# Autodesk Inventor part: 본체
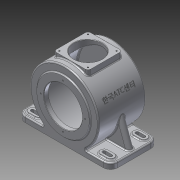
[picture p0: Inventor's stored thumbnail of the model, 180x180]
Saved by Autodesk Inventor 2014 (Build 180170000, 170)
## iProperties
Created: 2015-06
Part Number: 본체
Material: 알루미늄 6061
Document SubType Name: Modeling
Designer: basic
Density: 2.71 g/cm^3
Appearance: 알루미늄 - 평지
Mass: 3237.59 g
Surface Area: 2301.07 cm^2
Volume: 1194.68 cm^3
Author: basic
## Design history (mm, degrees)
sketch "스케치1"
  geometry: L1 (115, 7)-(-115, 7); L2 (-115, 7)-(-115, -7); L3 (-115, -7)-(115, -7); L4 (115, -7)-(115, 7); A1 r 85 centre (0, 78) between (46.733, 7) and (-46.733, 7); 3 further points
  constraints: 8 end point, 2 midpoint, 2 parallel, 2 point on circle, 2 point on line, 2 vertical alignment, 1 centre point, 1 horizontal, 1 horizontal alignment, 1 perpendicular
  dimensions: "d0" = 230 distance of L1.start L1.end; "d1" = 14 distance of L1.end L2.end; "d2" = 170 diameter of A1; "d3" = 85 distance from line of A1.centre L3
extrude "돌출1" new body sketch "스케치1" stored distance "d4" = 118; taper "d5" = 0 deg
sketch "스케치2"
  geometry: C1 r 65 at (0, 78); A1 r 85 centre (0, 78) between (46.733, 7) and (-46.733, 7) reference; 1 further point
  constraints: 1 centre point, 1 coincident
  dimensions: "d6" = 130 diameter of C1
extrude "돌출2" join sketch "스케치2" distance "d7" = 3; taper "d8" = 0 deg
sketch "스케치3"
  geometry: C1 r 65 at (0, -78); A1 r 85 centre (0, -78) between (-46.733, -7) and (46.733, -7) reference; 1 further point
  constraints: 1 centre point, 1 coincident
  dimensions: "d9" = 130 diameter of C1
extrude "돌출3" join sketch "스케치3" distance "d10" = 13; taper "d11" = 0 deg
node "작업 평면1"
sketch "스케치4"
  geometry: L1 (200, 0)-(30, 0) reference; L2 (157.5, -16.5)-(72.5, -16.5); L3 (72.5, -16.5)-(72.5, -101.5); L4 (72.5, -101.5)-(157.5, -101.5); L5 (157.5, -101.5)-(157.5, -16.5); 5 further points
  constraints: 8 end point, 2 midpoint, 2 parallel, 1 horizontal, 1 horizontal alignment, 1 perpendicular, 1 vertical alignment
  dimensions: "d13" = 85 distance of L4.end L3.end; "d14" = 85 distance of L3.end L2.end
extrude "돌출4" join sketch "스케치4" stored distance "d15" = 13; taper "d16" = 0 deg
sketch "스케치5"
  geometry: L1 (68.267, 0)-(68.267, 118) reference; L2 (0, 118)-(68.267, 118) reference; L3 (-161.733, 0)-(-161.733, 118) reference; L4 (68.267, 118)-(-161.733, 118) reference; L5 (68.267, 0)-(68.267, 118) reference; L6 (-161.733, 0)-(68.267, 0) reference; L7 (34.267, 109)-(50.267, 109); L8 (50.267, 91)-(34.267, 91); A1 r 9 centre (50.267, 100) between (50.267, 91) and (50.267, 109); A2 r 9 centre (34.267, 100) between (34.267, 109) and (34.267, 91); 1 further point
  constraints: 4 end point, 4 point on circle, 4 tangent, 2 centre point, 1 horizontal alignment
  dimensions: "d17" = 18 diameter of A1; "d18" = 18 diameter of A2; "d19" = 16 distance of A2.centre A1.centre; "d20" = 18 distance from line of A1.centre L1; "d21" = 18 distance from line of L2 A1.centre
extrude "돌출5" join sketch "스케치5" distance "d22" = 3; taper "d23" = 0 deg
sketch "스케치6"
  geometry: L1 (50.267, 109)-(34.267, 109) reference; L2 (34.267, 104)-(50.267, 104); L3 (50.267, 96)-(34.267, 96); A1 r 9 centre (34.267, 100) between (34.267, 109) and (34.267, 91) reference; A2 r 9 centre (50.267, 100) between (50.267, 91) and (50.267, 109) reference; A3 r 4 centre (50.267, 100) between (50.267, 96) and (50.267, 104); A4 r 4 centre (34.267, 100) between (34.267, 104) and (34.267, 96); 1 further point
  constraints: 4 end point, 4 point on circle, 3 tangent, 2 centre point, 2 coincident, 1 parallel
  dimensions: "d24" = 8 diameter of A3; "d25" = 8 diameter of A4
extrude "돌출6" cut sketch "스케치6" stored distance "d26" = 3; taper "d27" = 0 deg
sketch "스케치7"
  geometry: L1 (115, 7)-(46.733, 7) reference; L2 (-46.733, 7)-(-115, 7) reference; L3 (-115, 7)-(-115, -7) reference; L4 (-115, -7)-(115, -7) reference; L5 (115, -7)-(115, 7) reference; L6 (-109, 7)-(-84.87, 73.297); C1 r 65 at (0, 78) reference; A1 r 85 centre (0, 78) between (46.733, 7) and (-46.733, 7) reference; 1 further point
  constraints: 2 end point, 1 point on circle, 1 point on line
  dimensions: "d28" = 6 distance from line of L3 L6.start; "d29" = 110 deg angle of L2 L6
extrude "돌출7" join sketch "스케치7" stored distance "d30" = 15; taper "d31" = 0 deg
sketch "스케치8"
  geometry: L1 (115, 7)-(46.733, 7) reference; L2 (-46.733, 7)-(-115, 7) reference; L3 (-115, 7)-(-115, -7) reference; L4 (-115, -7)-(115, -7) reference; L5 (115, -7)-(115, 7) reference; C1 r 65 at (0, 78) reference; C2 r 77 at (0, 78); A1 r 85 centre (0, 78) between (46.733, 7) and (-46.733, 7) reference; 1 further point
  constraints: 1 centre point, 1 coincident
  dimensions: "d32" = 154 diameter of C2
extrude "돌출8" cut sketch "스케치8" stored distance "d33" = 102; taper "d34" = 0 deg
sketch "스케치9"
  geometry: C1 r 65 at (0, 0) reference; C2 r 47.5 at (0, 0); 1 further point
  constraints: 1 centre point, 1 coincident
  dimensions: "d35" = 95 diameter of C2
extrude "돌출9" cut sketch "스케치9" distance "d36" = 11; taper "d37" = 0 deg
sketch "스케치10"
  geometry: L1 (7.5, 73.297)-(7.5, 7) reference; L2 (59, 7)-(7.5, 7) reference; L3 (59, 7)-(59, 7) reference; L4 (-59, 7)-(59, 7) reference; L5 (-59, 7)-(-59, 7) reference; L6 (-7.5, 7)-(-59, 7) reference; L7 (-7.5, 7)-(-7.5, 73.297) reference; L8 (-7.5, 73.297)-(7.5, 73.297) reference; L9 (-42.5, 151.612)-(42.5, 151.612) reference; L10 (42.5, 151.612)-(42.5, 151.612) reference; L11 (42.5, 151.612)-(-42.5, 151.612) reference; L12 (-42.5, 151.612)-(-42.5, 151.612) reference; L13 (51, 1)-(51, 155) reference; L14 (-51, 125.5)-(-51, 30.5) reference; L15 (-62, 30.5)-(-62, 125.5) reference; L16 (47.5, 107.368)-(47.5, 78); L17 (47.5, 78)-(51, 78); L18 (51, 78)-(51, 109); L19 (51, 109)-(47.5, 107.368); 2 further points
  constraints: 8 end point, 1 horizontal, 1 horizontal alignment, 1 midpoint, 1 parallel, 1 point on line, 1 vertical
  dimensions: "d38" = 62 diameter of L18.end L17; "d39" = 115 deg angle of L13 L19; "d40" = 3.5 distance of L16.end L17.end
revolve "회전1" sketch "스케치10" stored, may be unused: angle "d41" = 90 deg
sketch "스케치11"
  geometry: C1 r 47.5 at (0, 0) reference; C2 r 23.5 at (0, 0); 1 further point
  constraints: 1 centre point, 1 coincident
  dimensions: "d42" = 47 diameter of C2
extrude "돌출10" cut sketch "스케치11" distance "d43" = 14; taper "d44" = 0 deg
sketch "스케치12"
  geometry: C1 r 23.5 at (0, 0) reference; C2 r 15 at (0, 0); 1 further point
  constraints: 1 centre point, 1 coincident
  dimensions: "d45" = 30 diameter of C2
extrude "돌출11" cut sketch "스케치12" distance "d46" = 3; taper "d47" = 0 deg
fillet "모깎기1" dims "d48" = 3, "d49" = 0.3
sketch "스케치13"
  geometry: C1 r 35 at (-115, -59); 1 further point
  constraints: 1 centre point, 1 coincident
  dimensions: "d50" = 70 diameter of C1
extrude "돌출12" cut sketch "스케치13" distance "d51" = 50; taper "d52" = 0 deg
sketch "스케치14"
  geometry: L1 (-150.5, -23.5)-(-79.5, -23.5); L2 (-79.5, -23.5)-(-79.5, -94.5); L3 (-79.5, -94.5)-(-150.5, -94.5); L4 (-150.5, -94.5)-(-150.5, -23.5); C1 r 35 at (-115, -59) reference; 3 further points
  constraints: 8 end point, 2 midpoint, 2 parallel, 1 coincident, 1 horizontal, 1 horizontal alignment, 1 perpendicular, 1 vertical alignment
  dimensions: "d53" = 71 distance of L2.end L3.end; "d54" = 71 distance of L1.end L2.end
hole "구멍1" sketch "스케치14" at (-79.5, -23.5) diameter "d55" = 3.242; stored, may be unused: countersink angle "d59" = 90 deg, drill point angle "d61" = 118 deg; dims "d56" = 10, "d57" = 47, "d58" = 14, "d60" = 13
sketch "스케치15"
  geometry: C1 r 47.5 at (0, 0) reference; 2 further points
  constraints: 1 vertical alignment
  dimensions: "d68" = 55 distance of C1.centre point (0, 55)
hole "구멍2" sketch "스케치15" at (0, 55) diameter "d69" = 3.242; stored, may be unused: countersink angle "d73" = 90 deg, drill point angle "d75" = 118 deg; dims "d70" = 11, "d71" = 47, "d72" = 14, "d74" = 13
fillet "모깎기2" dims "d79" = 7.5
fillet "모깎기3" dims "d80" = 7
fillet "모깎기6" dims "d83" = 18
fillet "모깎기7" dims "d84" = 3
fillet "모깎기8" dims "d85" = 3
fillet "모깎기9" dims "d86" = 3
fillet "모깎기10" dims "d87" = 3
fillet "모깎기11" dims "d88" = 3
fillet "모깎기12" dims "d89" = 3
fillet "모깎기13" dims "d90" = 3
node "작업 평면4"
  node "작업 평면3"
sketch "스케치16"
  geometry: L1 (11, 47.5)-(11, -47.5) reference; L2 (-26.8, 0)-(160.8, 0) reference; L3 (134, 62)-(134, -62) reference; L4 (0, 65)-(0, -65) reference; L5 (3, -79.424)-(3, 82) reference; L6 (121, 82)-(121, -79.424) reference; L7 (118, -82.329)-(118, 85) reference; 7 further points; 1 other entity
  constraints: 1 horizontal alignment, 1 midpoint, 1 vertical alignment, 2 other
feature "엠보싱1" sketch "스케치16" dims "d94" = 0.5, "d95" = 0
chamfer "모따기1" distance "d96" = 1; stored, may be unused: second distance "d97" = 2, angle "d98" = 45 deg
node "솔리드1"
mirror "대칭1"
mirror "대칭2"
pattern_linear "직사각형 패턴1" dims "d64" = 71, "d67" = 71
pattern_circular "원형 패턴1" dims angle "d77" = 360 deg
mirror "대칭3"
node "투영된 루프1"
node "투영된 루프2"
node "투영된 루프3"
node "투영된 루프4"
node "투영된 루프5"
node "작업 평면2"
node "작업축1"
node "투영된 루프6"
other parameters: "d12" = -173, "d91" = -85, "d92" = 65 deg, "d93" = -166
